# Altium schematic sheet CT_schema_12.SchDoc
size 281 x 153 mm
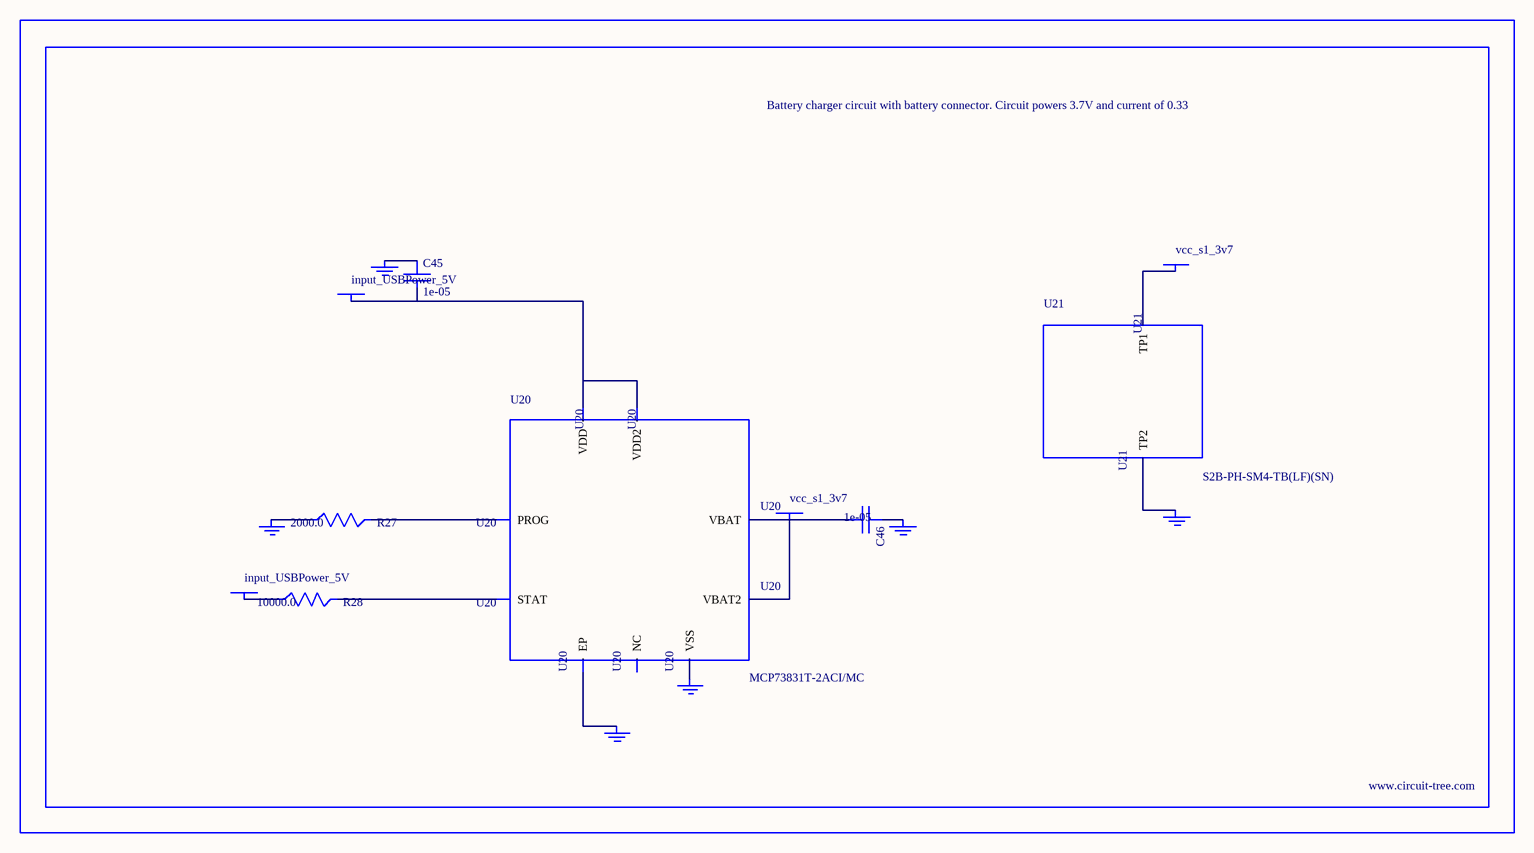
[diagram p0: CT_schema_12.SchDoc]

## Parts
BORDER11  (no value)
C45  1e-05  [C1206]
C46  1e-05  [C1206]
GND_INSTANCE_11_0  (no value)
GND_INSTANCE_11_1  (no value)
GND_INSTANCE_11_2  (no value)
GND_INSTANCE_11_3  (no value)
GND_INSTANCE_11_4  (no value)
GND_INSTANCE_11_5  (no value)
POWER_INSTANCE_11_0  input_USBPower_5V
POWER_INSTANCE_11_1  input_USBPower_5V
POWER_INSTANCE_11_2  vcc_s1_3v7
POWER_INSTANCE_11_3  vcc_s1_3v7
R27  2000.0  [R0603]
R28  10000.0  [R0603]
U20  MCP73831T-2ACI/MC  [DFN8_2X3MC]
U21  S2B-PH-SM4-TB(LF)(SN)  [JST-2-SMD]

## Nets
NetC45_1: C45.1 GND_INSTANCE_11_0.0(GND)
NetC45_2: C45.2 POWER_INSTANCE_11_0.0(PWR) U20.1(VDD) U20.2(VDD2)
NetC46_1: C46.1 GND_INSTANCE_11_1.0(GND)
NetC46_2: C46.2 POWER_INSTANCE_11_2.0(PWR) U20.3(VBAT) U20.4(VBAT2)
NetGND_INSTANCE_11_2_0: GND_INSTANCE_11_2.0(GND) R27.1
NetGND_INSTANCE_11_3_0: GND_INSTANCE_11_3.0(GND) U20.9(EP)
NetGND_INSTANCE_11_4_0: GND_INSTANCE_11_4.0(GND) U20.6(VSS)
NetGND_INSTANCE_11_5_0: GND_INSTANCE_11_5.0(GND) U21.2(TP2)
NetPOWER_INSTANCE_11_1_0: POWER_INSTANCE_11_1.0(PWR) R28.1
NetPOWER_INSTANCE_11_3_0: POWER_INSTANCE_11_3.0(PWR) U21.1(TP1)
NetR27_2: R27.2 U20.8(PROG)
NetR28_2: R28.2 U20.5(STAT)

Not connected (* = marked no-connect by the designer): U20 7(NC)

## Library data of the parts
BORDER11 = BORDER_PAGE11
C45 C46 = C1206C106K3RACTU
GND_INSTANCE_11_0-GND_INSTANCE_11_5 = GND
POWER_INSTANCE_11_0-POWER_INSTANCE_11_3 = PWR
R27 = RC0603JR-072KL
R28 = RC0603JR-0710KL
